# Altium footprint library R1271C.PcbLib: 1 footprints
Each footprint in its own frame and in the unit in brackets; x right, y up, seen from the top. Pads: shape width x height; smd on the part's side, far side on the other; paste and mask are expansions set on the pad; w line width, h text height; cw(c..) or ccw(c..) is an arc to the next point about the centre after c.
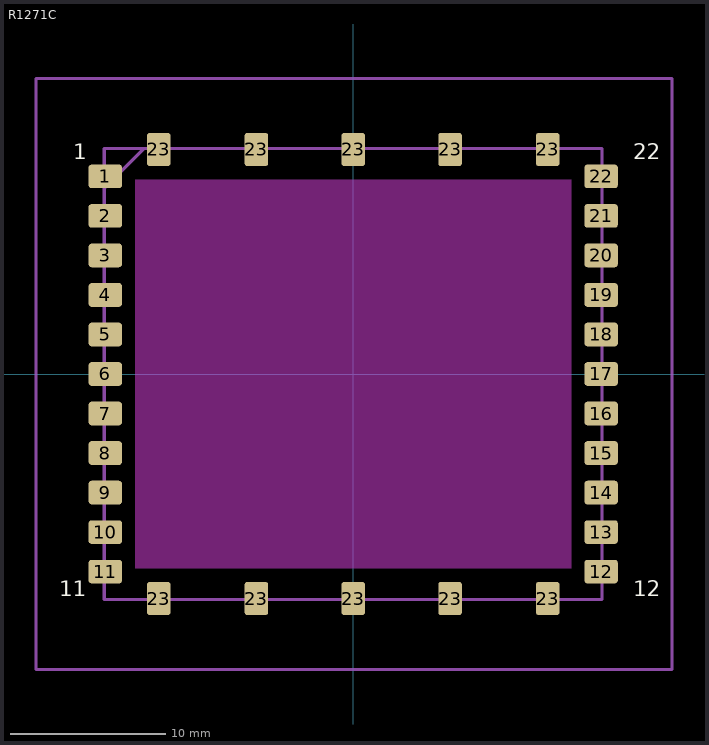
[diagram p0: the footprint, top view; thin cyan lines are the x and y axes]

## R1271C [mil]
pads (32):
  rrect25% 84.6x59.8 smd: 1(-627.2,500) 2(-627.2,400) 3(-627.2,300) 4(-627.2,200) 5(-627.2,100) 6(-627.2,0) 7(-627.2,-100) 8(-627.2,-200) 9(-627.2,-300) 10(-627.2,-400) 11(-627.2,-500) 12(627.2,-500) 13(627.2,-400) 14(627.2,-300) 15(627.2,-200) 16(627.2,-100) 17(627.2,0) 18(627.2,100) 19(627.2,200) 20(627.2,300) 21(627.2,400) 22(627.2,500)
  rrect25% 59.8x84.6 smd: 23(-492.1,-568.1) 23(-492.1,568.1) 23(-245.1,-568.1) 23(-245.1,568.1) 23(0,-568.1) 23(0,568.1) 23(245.1,-568.1) 23(245.1,568.1) 23(492.1,-568.1) 23(492.1,568.1)
Top Layer keep-out:
  region: -551.18,492.13 551.18,492.13 551.18,-492.13 -551.18,-492.13
Top Overlay:
  text ".Designator" at -613,645.67 h118.11
  text "1" at -709,543 h39.37
  text "11" at -744,-562 h39.37
  text "12" at 708.66,-562.99 h39.37
  text "22" at 709,542.99 h39.37
Mechanical 2:
  lines w7.87: -629.92,-570.87 629.92,-570.87 629.92,570.87 -629.92,570.87 -629.92,-570.87
Top Assy:
  lines w7.87: -628.87,471 -529,570.87 ; -629.92,-570.87 -629.92,570.87 629.92,570.87 629.92,-570.87 -629.92,-570.87
  lines w10: -630,352 -630,356.87
  text ".Designator" at -259,-28 h118.11
Top Court:
  lines w7.87: -803.15,-748.03 -803.15,748.03 807.09,748.03 807.09,-748.03 -803.15,-748.03
3D body "R1271C.step": height 157.09, standoff 0, extent -629.91,-570.86 629.92,570.87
